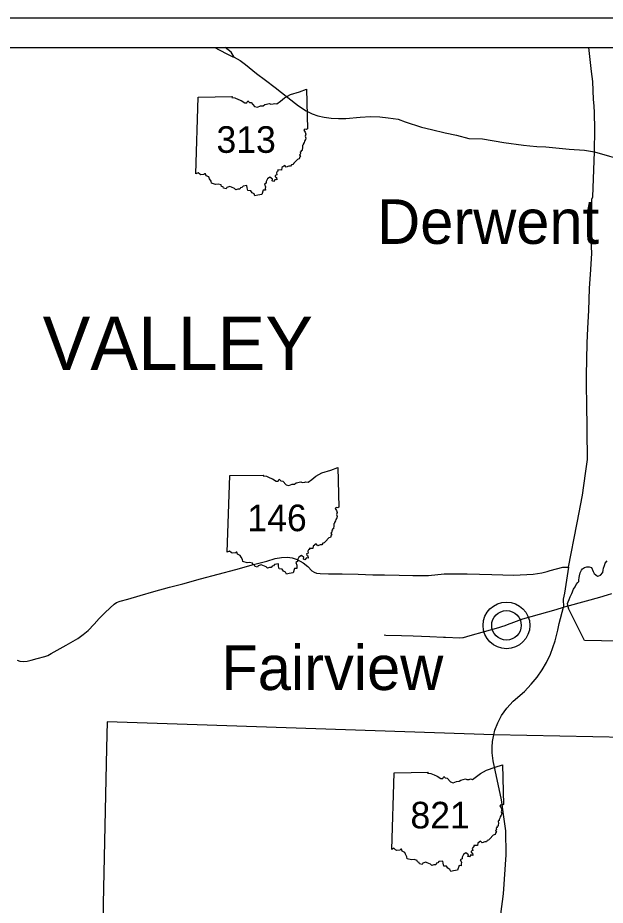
# Model space of a CAD drawing. Extents: x 0 to 34, y 0 to 22.
# Drawn here: x 24.277 to 26.145, y 17.734 to 20.557 of the extents above; entities that cross this region are included whole.
import ezdxf

# ---------------------------------------------------------------- set-up
doc = ezdxf.new("R2010")
doc.units = 0
for name, color, linetype in [('Default', 7, 'Continuous'), ('GM_X_Corporation', 7, 'Continuous'), ('GM_X_State_Route', 7, 'Continuous'), ('GM_X_Township', 7, 'Continuous'), ('GM_X_Township_Road', 7, 'Continuous'), ('GM_X_Township_Text', 7, 'Continuous'), ('GM_X_Unincorporated', 7, 'Continuous'), ('GM_X_Unincorporated_Text', 7, 'Continuous')]:
    doc.layers.add(name, color=color, linetype=linetype)

msp = doc.modelspace()

# ---------------------------------------------------------------- linework, layer by layer
at = {"layer": 'Default'}
for p, q in [((19.8526, 20.4625), (30.697, 20.4625)), ((24.8432, 20.0604), (24.8511, 20.3045)), ((24.9431, 18.8569), (24.951, 19.1009)), ((25.4663, 17.9114), (25.4741, 18.1555))]:
    msp.add_line(p, q, dxfattribs=at)
msp.add_lwpolyline([(19.7581, 20.557), (30.7915, 20.557), (30.7915, 9.5237), (19.7581, 9.5237)], close=True, dxfattribs=at)
for points in [[(24.8511, 20.3045), (24.9592, 20.306), (24.9576, 20.3031), (24.9677, 20.3025), (24.9786, 20.2972), (24.9878, 20.294), (24.9989, 20.2862), (25.0057, 20.2863), (25.0085, 20.2927), (25.0137, 20.2878), (25.0198, 20.2869), (25.0303, 20.2752), (25.0391, 20.2727), (25.0495, 20.2767), (25.0572, 20.2773), (25.0629, 20.2813), (25.0778, 20.2847), (25.082, 20.2826), (25.0898, 20.2831), (25.0938, 20.2846), (25.1007, 20.2832), (25.1126, 20.2921), (25.1251, 20.3025), (25.1442, 20.3124), (25.1727, 20.3218), (25.1953, 20.3301), (25.1986, 20.2035)], [(25.1986, 20.2035), (25.1953, 20.2017), (25.1901, 20.2025), (25.1866, 20.199), (25.1909, 20.1931), (25.1929, 20.1868), (25.1911, 20.1799), (25.1929, 20.1742), (25.1917, 20.1695), (25.1885, 20.1647), (25.1874, 20.1602), (25.1846, 20.1554), (25.1848, 20.1528), (25.1822, 20.1507), (25.1826, 20.1427), (25.1813, 20.1384), (25.1818, 20.1346), (25.1774, 20.1336), (25.1784, 20.1305), (25.1757, 20.128), (25.1763, 20.1239), (25.1732, 20.1212), (25.1762, 20.1159), (25.1738, 20.1142), (25.1718, 20.1078), (25.1663, 20.1064), (25.1554, 20.0947), (25.1514, 20.0902), (25.1471, 20.0891), (25.1446, 20.0845), (25.1393, 20.0845), (25.1311, 20.0813), (25.1259, 20.0868), (25.1167, 20.0802), (25.1156, 20.0725), (25.1041, 20.0728), (25.1045, 20.0689), (25.1019, 20.0678), (25.0995, 20.064), (25.1009, 20.0571), (25.0954, 20.0554), (25.0961, 20.0514), (25.0996, 20.049), (25.1011, 20.0414), (25.0953, 20.0429), (25.0906, 20.0365), (25.0857, 20.038), (25.0873, 20.0434), (25.079, 20.05), (25.0713, 20.0448), (25.0672, 20.0364), (25.0671, 20.0308), (25.0613, 20.0274), (25.0651, 20.0195), (25.0643, 20.014), (25.0645, 20.0087), (25.0572, 20.009), (25.0528, 19.9949)], [(25.0528, 19.9949), (25.0402, 19.9923), (25.0315, 19.9907), (25.0284, 19.997), (25.0221, 20.0004), (25.018, 20.0068), (25.009, 20.0076), (25.0069, 20.0165), (25.0059, 20.0236), (24.9936, 20.0218), (24.9902, 20.0175), (24.9858, 20.0163), (24.9833, 20.0119), (24.9773, 20.0115), (24.9709, 20.0094), (24.9667, 20.0138), (24.9563, 20.0181), (24.9516, 20.0203), (24.9417, 20.0169), (24.9397, 20.0128), (24.9319, 20.0146), (24.93, 20.0192), (24.9253, 20.0206), (24.9242, 20.0254), (24.9141, 20.028), (24.9063, 20.027), (24.8927, 20.0309), (24.8918, 20.0373), (24.8872, 20.0451), (24.8849, 20.0505), (24.8762, 20.0546), (24.8744, 20.061), (24.8717, 20.0608), (24.8692, 20.0582), (24.8595, 20.057), (24.8557, 20.0596), (24.8503, 20.0642), (24.8432, 20.0604)], [(24.951, 19.1009), (25.0591, 19.1025), (25.0575, 19.0995), (25.0676, 19.099), (25.0785, 19.0937), (25.0877, 19.0905), (25.0989, 19.0827), (25.1056, 19.0828), (25.1084, 19.0892), (25.1136, 19.0842), (25.1197, 19.0834), (25.1303, 19.0716), (25.139, 19.0691), (25.1494, 19.0732), (25.1571, 19.0738), (25.1629, 19.0778), (25.1777, 19.0811), (25.1819, 19.0791), (25.1897, 19.0796), (25.1937, 19.081), (25.2006, 19.0797), (25.2125, 19.0886), (25.225, 19.099), (25.2441, 19.1089), (25.2726, 19.1182), (25.2952, 19.1266), (25.2985, 18.9999)], [(25.2985, 18.9999), (25.2952, 18.9982), (25.29, 18.999), (25.2865, 18.9955), (25.2909, 18.9896), (25.2928, 18.9833), (25.2911, 18.9764), (25.2928, 18.9707), (25.2916, 18.9659), (25.2884, 18.9612), (25.2873, 18.9567), (25.2845, 18.9519), (25.2847, 18.9492), (25.2821, 18.9472), (25.2825, 18.9392), (25.2812, 18.9349), (25.2817, 18.9311), (25.2773, 18.9301), (25.2783, 18.9269), (25.2756, 18.9245), (25.2762, 18.9204), (25.2731, 18.9177), (25.2761, 18.9124), (25.2737, 18.9107), (25.2717, 18.9042), (25.2662, 18.9029), (25.2553, 18.8911), (25.2513, 18.8867), (25.247, 18.8855), (25.2445, 18.8809), (25.2392, 18.8809), (25.231, 18.8777), (25.2258, 18.8832), (25.2166, 18.8766), (25.2155, 18.869), (25.204, 18.8692), (25.2044, 18.8654), (25.2018, 18.8643), (25.1994, 18.8605), (25.2008, 18.8536), (25.1953, 18.8518), (25.196, 18.8479), (25.1995, 18.8455), (25.201, 18.8379), (25.1952, 18.8394), (25.1905, 18.833), (25.1856, 18.8345), (25.1872, 18.8399), (25.179, 18.8465), (25.1712, 18.8412), (25.1671, 18.8329), (25.167, 18.8272), (25.1612, 18.8238), (25.165, 18.8159), (25.1642, 18.8105), (25.1644, 18.8052), (25.1571, 18.8054), (25.1527, 18.7914)], [(25.1527, 18.7914), (25.1401, 18.7887), (25.1314, 18.7872), (25.1283, 18.7935), (25.122, 18.7969), (25.1179, 18.8032), (25.1089, 18.8041), (25.1068, 18.813), (25.1058, 18.8201), (25.0935, 18.8183), (25.0901, 18.8139), (25.0857, 18.8128), (25.0832, 18.8084), (25.0772, 18.808), (25.0708, 18.8059), (25.0667, 18.8102), (25.0562, 18.8146), (25.0515, 18.8168), (25.0416, 18.8134), (25.0396, 18.8092), (25.0318, 18.811), (25.0299, 18.8156), (25.0252, 18.817), (25.0241, 18.8219), (25.014, 18.8245), (25.0062, 18.8234), (24.9926, 18.8273), (24.9917, 18.8337), (24.9871, 18.8415), (24.9848, 18.847), (24.9761, 18.851), (24.9743, 18.8575), (24.9716, 18.8573), (24.9691, 18.8547), (24.9594, 18.8535), (24.9556, 18.8561), (24.9502, 18.8606), (24.9431, 18.8569)], [(25.8267, 18.6242), (25.8343, 18.627), (25.8834, 18.6445), (25.9891, 18.6752), (26.0129, 18.6821)], [(25.4424, 18.5936), (25.4473, 18.5931), (25.4978, 18.5922), (25.5346, 18.5907), (25.5874, 18.5886), (25.6311, 18.5868), (25.6374, 18.5866), (25.683, 18.5851), (25.6924, 18.5856), (25.6943, 18.5857), (25.7163, 18.5919), (25.8066, 18.6177), (25.8135, 18.6197), (25.8163, 18.6205), (25.8267, 18.6242)], [(25.4741, 18.1555), (25.5823, 18.157), (25.5806, 18.1541), (25.5908, 18.1535), (25.6017, 18.1483), (25.6108, 18.145), (25.622, 18.1372), (25.6287, 18.1373), (25.6316, 18.1437), (25.6367, 18.1388), (25.6428, 18.1379), (25.6534, 18.1262), (25.6621, 18.1237), (25.6726, 18.1277), (25.6803, 18.1283), (25.686, 18.1323), (25.7009, 18.1357), (25.705, 18.1336), (25.7129, 18.1341), (25.7169, 18.1356), (25.7237, 18.1342), (25.7357, 18.1431), (25.7482, 18.1535), (25.7673, 18.1634), (25.7958, 18.1728), (25.8184, 18.1811), (25.8217, 18.0545)], [(25.8217, 18.0545), (25.8183, 18.0527), (25.8132, 18.0535), (25.8097, 18.05), (25.814, 18.0441), (25.816, 18.0378), (25.8142, 18.031), (25.816, 18.0252), (25.8148, 18.0205), (25.8116, 18.0157), (25.8104, 18.0112), (25.8076, 18.0064), (25.8078, 18.0038), (25.8052, 18.0017), (25.8057, 17.9938), (25.8044, 17.9894), (25.8048, 17.9856), (25.8005, 17.9846), (25.8015, 17.9815), (25.7988, 17.979), (25.7994, 17.9749), (25.7963, 17.9722), (25.7993, 17.9669), (25.7969, 17.9652), (25.7949, 17.9588), (25.7893, 17.9574), (25.7784, 17.9457), (25.7745, 17.9412), (25.7702, 17.9401), (25.7677, 17.9355), (25.7624, 17.9355), (25.7542, 17.9323), (25.749, 17.9378), (25.7398, 17.9312), (25.7387, 17.9236), (25.7271, 17.9238), (25.7275, 17.9199), (25.7249, 17.9188), (25.7226, 17.915), (25.7239, 17.9081), (25.7185, 17.9064), (25.7192, 17.9024), (25.7227, 17.9), (25.7242, 17.8924), (25.7184, 17.8939), (25.7137, 17.8875), (25.7088, 17.889), (25.7104, 17.8944), (25.7021, 17.901), (25.6943, 17.8958), (25.6903, 17.8874), (25.6902, 17.8818), (25.6844, 17.8784), (25.6882, 17.8705), (25.6874, 17.865), (25.6876, 17.8598), (25.6803, 17.86), (25.6758, 17.846)], [(25.6758, 17.846), (25.6633, 17.8433), (25.6546, 17.8417), (25.6514, 17.8481), (25.6452, 17.8514), (25.641, 17.8578), (25.6321, 17.8586), (25.6299, 17.8675), (25.6289, 17.8746), (25.6166, 17.8728), (25.6133, 17.8685), (25.6089, 17.8673), (25.6064, 17.8629), (25.6004, 17.8625), (25.594, 17.8604), (25.5898, 17.8648), (25.5794, 17.8691), (25.5747, 17.8713), (25.5648, 17.8679), (25.5627, 17.8638), (25.555, 17.8656), (25.5531, 17.8702), (25.5484, 17.8716), (25.5473, 17.8764), (25.5372, 17.879), (25.5294, 17.878), (25.5158, 17.8819), (25.5149, 17.8883), (25.5103, 17.8961), (25.5079, 17.9015), (25.4993, 17.9056), (25.4975, 17.912), (25.4948, 17.9119), (25.4922, 17.9092), (25.4826, 17.908), (25.4788, 17.9106), (25.4734, 17.9152), (25.4663, 17.9114)]]:
    msp.add_lwpolyline(points, dxfattribs=at)
at = {"layer": 'GM_X_Corporation'}
msp.add_lwpolyline([(26.6742, 18.5648), (26.0789, 18.5761), (26.0299, 18.6761), (26.0275, 18.6835), (26.0263, 18.6883), (26.0257, 18.6934), (26.0272, 18.6996), (26.0301, 18.706), (26.034, 18.7154), (26.0394, 18.7261), (26.0444, 18.7391), (26.0495, 18.7466), (26.0527, 18.7538), (26.0581, 18.7603), (26.061, 18.7639), (26.0614, 18.7682), (26.0624, 18.7768), (26.0639, 18.7822), (26.0657, 18.7909), (26.0696, 18.7995), (26.0725, 18.8038), (26.079, 18.8081), (26.0869, 18.8103), (26.0944, 18.8103), (26.1013, 18.8085), (26.107, 18.7959), (26.1096, 18.7887), (26.1203, 18.7812), (26.125, 18.7822), (26.1301, 18.7844), (26.1372, 18.7927), (26.139, 18.7995), (26.1401, 18.8067), (26.1434, 18.8146), (26.1452, 18.8218), (26.1516, 18.83)], dxfattribs=at)
at = {"layer": 'GM_X_State_Route'}
for points in [[(24.9042, 20.4625), (24.9153, 20.4565), (24.946, 20.4396), (24.9609, 20.4325), (24.9655, 20.4316), (24.9841, 20.4208), (25.0017, 20.4078), (25.0367, 20.3799), (25.0645, 20.3589), (25.0961, 20.3347), (25.1363, 20.3038), (25.1704, 20.2765), (25.1939, 20.2604), (25.2136, 20.2513), (25.2316, 20.245), (25.2514, 20.2408), (25.274, 20.2379), (25.2969, 20.2365), (25.3205, 20.2369), (25.3664, 20.2408), (25.3992, 20.2425), (25.4282, 20.2422), (25.4546, 20.239), (25.4867, 20.2344), (25.5086, 20.2256), (25.5607, 20.2087), (25.5925, 20.2015), (25.6365, 20.1914), (25.6726, 20.1831), (25.7113, 20.1734), (25.7548, 20.1721), (25.8226, 20.1604), (25.8849, 20.1518), (25.9059, 20.1495), (25.9277, 20.1471), (25.9566, 20.1469), (25.9885, 20.1427), (26.0302, 20.1388), (26.0797, 20.1356), (26.1116, 20.131)], [(26.0552, 18.9453), (26.0562, 18.9507), (26.0728, 19.0384), (26.0827, 19.1071), (26.0885, 19.1518), (26.0864, 19.3359), (26.0856, 19.3786), (26.0856, 19.4192), (26.0882, 19.5216), (26.0904, 19.5691), (26.0929, 19.6256), (26.0958, 19.696), (26.0997, 19.7561), (26.1026, 19.8085), (26.101, 19.8489), (26.0985, 19.8919), (26.0985, 19.918), (26.1001, 19.9379), (26.1027, 19.98), (26.106, 19.9872), (26.1116, 20.131), (26.112, 20.2023), (26.1108, 20.2545), (26.1101, 20.2764), (26.1084, 20.2969), (26.1057, 20.3545), (26.1033, 20.3698), (26.1018, 20.3861), (26.0933, 20.4625)], [(26.1116, 20.131), (26.1587, 20.117), (26.1735, 20.1123), (26.2055, 20.1018), (26.2229, 20.0971), (26.2383, 20.093), (26.2686, 20.0831), (26.304, 20.0721), (26.3379, 20.0605), (26.438, 20.0307), (26.508, 20.0021), (26.5232, 19.9972), (26.5497, 19.9886), (26.5557, 19.9868), (26.5892, 19.9766), (26.601, 19.9726), (26.608, 19.9703), (26.6318, 19.9623), (26.6589, 19.9536), (26.7253, 19.9377), (26.7495, 19.9297)], [(26.0286, 18.8091), (26.0552, 18.9453)], [(24.275, 18.5138), (24.2833, 18.5102), (24.2962, 18.5092), (24.3071, 18.5108), (24.3196, 18.514), (24.3388, 18.5192), (24.3633, 18.5247), (24.3727, 18.5286), (24.3832, 18.5344), (24.4024, 18.5449), (24.4309, 18.5615), (24.4677, 18.5828), (24.4854, 18.5951), (24.5007, 18.6082), (24.5205, 18.6285), (24.5365, 18.6465), (24.5541, 18.6637), (24.5706, 18.6798), (24.584, 18.6921), (24.5915, 18.6971), (24.6028, 18.701), (24.6273, 18.7081), (24.6665, 18.7196), (24.7102, 18.7318), (24.7596, 18.7453), (24.8018, 18.7568), (24.8583, 18.7718), (24.9149, 18.7869), (24.9707, 18.8023), (25.0272, 18.8178), (25.0687, 18.8289), (25.0954, 18.8368), (25.1154, 18.8404), (25.1351, 18.841), (25.1502, 18.8389), (25.1654, 18.8335), (25.1852, 18.8231), (25.1997, 18.8111), (25.2127, 18.798), (25.2196, 18.7932), (25.2272, 18.7903), (25.2393, 18.7889), (25.2658, 18.7885), (25.3085, 18.7878), (25.36, 18.7866), (25.4062, 18.7852), (25.4432, 18.7845), (25.4901, 18.7836), (25.5336, 18.7829), (25.5828, 18.7824), (25.6334, 18.788), (25.706, 18.788), (25.7846, 18.7865), (25.8545, 18.7842), (25.916, 18.7868), (25.9441, 18.7914), (25.9602, 18.7959)], [(25.9602, 18.7959), (25.9697, 18.7986), (26.0102, 18.8091), (26.0286, 18.8091)], [(26.0286, 18.8091), (26.0286, 18.8091), (26.0178, 18.7407)], [(26.0178, 18.7407), (26.0157, 18.7271), (26.0116, 18.7076), (26.0129, 18.6821)], [(26.0321, 18.6873), (26.1281, 18.7141), (26.1526, 18.721), (26.1662, 18.7251)], [(25.791, 18.2762), (25.7946, 18.2913), (25.8036, 18.314), (25.815, 18.3372), (25.832, 18.3609), (25.8524, 18.3827), (25.8888, 18.4144), (25.9096, 18.4371), (25.9286, 18.4599), (25.9447, 18.4826), (25.9585, 18.5066), (25.9712, 18.5327), (25.9866, 18.5749), (25.9944, 18.6092), (25.9992, 18.6302), (26.0129, 18.6821)], [(26.0129, 18.6821), (26.0269, 18.6859), (26.0321, 18.6873)], [(25.8049, 17.6409), (25.8218, 17.7707), (25.8303, 17.8939), (25.8288, 17.9702), (25.8226, 18.0152), (25.815, 18.0696), (25.7892, 18.1929), (25.7861, 18.2192), (25.7857, 18.237), (25.7871, 18.2544), (25.791, 18.2762)]]:
    msp.add_lwpolyline(points, dxfattribs=at)
at = {"layer": 'GM_X_Township'}
for p, q in [((24.5609, 18.3174), (24.5592, 18.2337)), ((24.8475, 18.3078), (24.5609, 18.3174)), ((25.791, 18.2762), (24.8475, 18.3078)), ((26.2248, 18.2671), (25.791, 18.2762)), ((24.5592, 18.2337), (24.5489, 17.738)), ((24.5489, 17.738), (24.5285, 16.7562))]:
    msp.add_line(p, q, dxfattribs=at)
at = {"layer": 'GM_X_Township_Road'}
msp.add_lwpolyline([(24.9655, 20.4316), (24.9553, 20.4474), (24.9463, 20.4554), (24.9362, 20.4625)], dxfattribs=at)
at = {"layer": 'GM_X_Unincorporated'}
for radius in [0.0742, 0.0471]:
    msp.add_circle((25.8313, 18.6243), radius, dxfattribs=at)

# ---------------------------------------------------------------- texts
at = {"layer": 'Default'}
for s, p in [('313', (24.909, 20.1273)), ('146', (25.0073, 18.9238)), ('821', (25.5259, 17.9783))]:
    msp.add_text(s, height=0.08462, dxfattribs=at).set_placement(p)
at = {"layer": 'GM_X_Township_Text'}
msp.add_text('VALLEY', height=0.1701, rotation=0, dxfattribs=at).set_placement((24.3562, 19.4365))
at = {"layer": 'GM_X_Unincorporated_Text'}
for s, p in [('Derwent', (25.4201, 19.8377)), ('Fairview', (24.9246, 18.4186))]:
    msp.add_text(s, height=0.14175, rotation=0, dxfattribs=at).set_placement(p)

doc.saveas('drawing.dxf')
